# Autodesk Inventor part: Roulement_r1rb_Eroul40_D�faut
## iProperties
Created: 2011-01
Part Number: Roulement_r1rb_Eroul40_D�faut
Document SubType Name: Modeling
Designer: eric
Density: 1 g/cm^3
Mass: 0.172007 g
Surface Area: 1.49571 cm^2
Volume: 0.172007 cm^3
Author: eric
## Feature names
1. Base1
